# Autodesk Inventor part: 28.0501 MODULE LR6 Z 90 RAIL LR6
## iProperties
Created: 2007-07
Part Number: 28.0501 MODULE LR6 Z 90 RAIL LR6
Material: Aluminum-6061
Document SubType Name: Modeling
Designer: Andy Moles
Density: 2.71 g/cm^3
Author: Andy Moles
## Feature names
1. Extrusion1
2. Hole1
3. Rectangular Pattern1
